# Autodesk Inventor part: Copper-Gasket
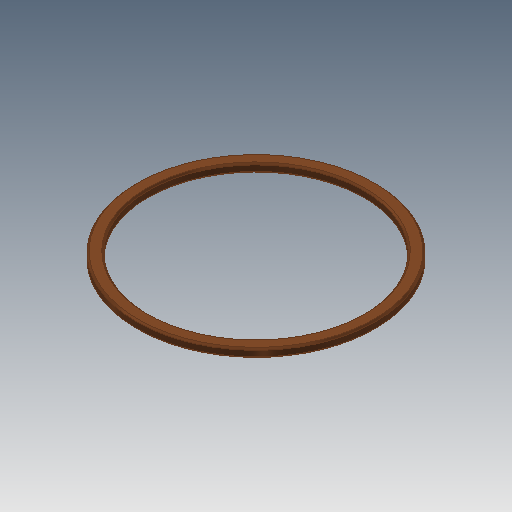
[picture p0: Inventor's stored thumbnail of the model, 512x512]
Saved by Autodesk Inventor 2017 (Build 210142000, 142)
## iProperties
Shininess: 64.0
Length Units: 11269
Angle Units: 11279
Time Units: 11290
Mass Units: 11283
Length Display Precision: 3
Angle Display Precision: 2
Compacted: True
Part Number: Copper-Gasket
Document SubType Name: Modeling
Created: 2004-01
Designer: Administrator
Manufacturer: Standard
Standards Organization: Custom
Density: 1 g/cm^3
Material: Generic
Appearance: Copper
Density: 0.0
Volumn: 0.0
Area: 0.0
PropertySet Name: Model Information
Control State: 0
Master: False
Checked Out: False
Author: Administrator
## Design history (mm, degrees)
sketch "Sketch1"
  geometry: L1 (-16.5, 1)-(-16.5, -0.456); L2 (-16.5, -0.456)-(-18.5, -0.456); L3 (-18.5, -0.456)-(-18.5, 1); L4 (1.5, -4.265)-(1.5, 4.737); L5 (-18.5, 1)-(-16.5, 1)
  constraints: 10 end point, 2 parallel, 1 perpendicular
  dimensions: "d4" = 18 distance between parallel lines of L4 L1
revolve "Revolution1" sketch "Sketch1" stored, may be unused: angle "d0" = 90 deg
chamfer "Chamfer1" distance "d1" = 0.25; stored, may be unused: second distance "d2" = 2, angle "d3" = 45 deg
body "Solid1"
